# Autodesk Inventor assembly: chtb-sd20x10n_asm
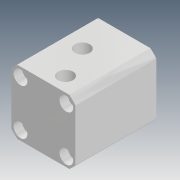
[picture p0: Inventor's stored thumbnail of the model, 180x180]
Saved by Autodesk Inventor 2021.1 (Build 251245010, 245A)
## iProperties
Company: Microsoft
Created: 2018-04
Part Number: chtb-sd20x10n_asm
Description: STEP AP214
Document SubType Name: Assembly
Designer: user
Title: chtb-sd20x10n_asm.STEP
Author: Windows
Revision Number: ÈÎºÎ
Sending System: SolidWorks 2015
Preprocessor: SwSTEP 2.0
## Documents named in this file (4)
- D:\Vault_2016\Projekty\Clamptek\Hydraulic\CHTB\CHTB-20\Inventor\CHTB-SD20x10N\chtb-sd20x10n_asm.iam
- D:\Vault_2016\Projekty\Clamptek\Hydraulic\CHTB\CHTB-20\Inventor\CHTB-SD20x10N\CHTB-SD20X10NBT.ipt
- D:\Vault_2016\Projekty\Clamptek\Hydraulic\CHTB\CHTB-20\Inventor\CHTB-SD20x10N\CHTB-SD20X10NHSG.ipt
- D:\Vault_2016\Projekty\Clamptek\Hydraulic\CHTB\CHTB-20\Inventor\CHTB-SD20x10N\QG.ipt
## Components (3 placed, 3 different names)
1. CHTB-SD20X10NBT_1
2. CHTB-SD20X10NHSG_2
3. QG_3
